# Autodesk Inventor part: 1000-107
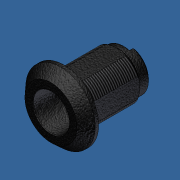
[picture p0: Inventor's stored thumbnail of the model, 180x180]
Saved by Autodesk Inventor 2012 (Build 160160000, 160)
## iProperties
Created: 2013-06
Part Number: 1000-107
Material: Default
Document SubType Name: Modeling
Designer: Admin
Density: 1 g/cm^3
Mass: 7.48812 g
Surface Area: 53.7927 cm^2
Volume: 7.48812 cm^3
Author: Admin
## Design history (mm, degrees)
node "1000-1071"
thread "Thread1" dims "d0" = 10, "d1" = 0
thread "Thread2" dims "d2" = 10, "d3" = 0
thread "Thread3" dims "d4" = 10, "d5" = 0
thread "Thread4" dims "d6" = 10, "d7" = 0
node "1000-107"
node "Base1"
